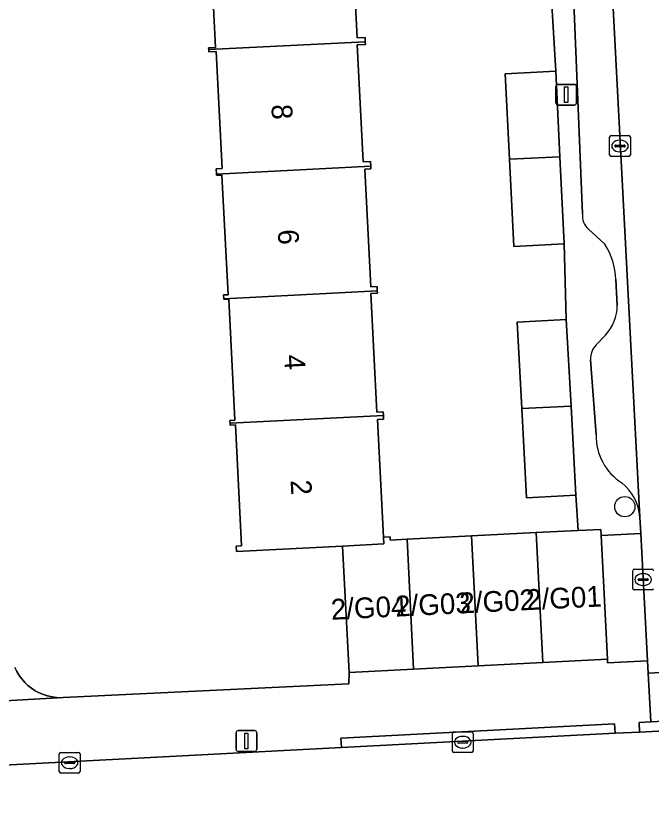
# Model space of a CAD drawing. Extents: x 161084 to 161928, y 385354 to 386522.
# Drawn here: x 161567.76 to 161598.42, y 385454.78 to 385493.46 of the extents above; entities that cross this region are included whole.
import ezdxf

# ---------------------------------------------------------------- set-up
doc = ezdxf.new("R2010")
doc.units = 0
for name, color, linetype in [('IMGEO_Boom', 7, 'Continuous'), ('IMGEO_Erf', 7, 'Continuous'), ('IMGEO_Kolk', 7, 'Continuous'), ('IMGEO_Lichtmast', 7, 'Continuous'), ('IMGEO_Pand', 7, 'Continuous'), ('IMGEO_Pand_nummerreeks', 7, 'Continuous'), ('IMGEO_Parkeervlak_open', 7, 'Continuous'), ('IMGEO_Rijbaan_lokaal_open', 7, 'Continuous'), ('IMGEO_Voetpad_open', 7, 'Continuous')]:
    doc.layers.add(name, color=color, linetype=linetype)

msp = doc.modelspace()

# ---------------------------------------------------------------- linework, layer by layer
at = {"layer": 'IMGEO_Boom'}
msp.add_circle((161597.107, 385469.791), 0.489, dxfattribs=at)
at = {"layer": 'IMGEO_Erf'}
for points in [[(161583.916, 385498.009), (161584.2, 385492.402), (161584.585, 385492.421), (161584.595, 385492.218), (161584.602, 385492.089), (161584.205, 385492.069), (161584.491, 385486.417), (161584.85, 385486.436), (161584.862, 385486.207), (161584.868, 385486.08), (161584.577, 385486.065), (161584.864, 385480.394), (161585.162, 385480.41), (161585.173, 385480.197), (161585.179, 385480.092), (161584.867, 385480.076), (161585.157, 385474.355), (161585.461, 385474.37), (161585.47, 385474.188), (161585.479, 385474.017), (161585.184, 385474.002), (161585.471, 385468.323), (161585.787, 385468.339), (161585.795, 385468.182), (161586.609, 385468.223), (161589.723, 385468.381), (161592.837, 385468.538), (161594.865, 385468.641), (161594.75, 385470.341), (161592.373, 385470.211), (161592.137, 385474.525), (161591.909, 385478.691), (161594.285, 385478.821), (161594.19, 385482.466), (161591.761, 385482.345), (161591.551, 385486.545), (161591.345, 385490.674), (161593.774, 385490.795), (161593.561, 385494.542)], [(161567.694, 385462.035), (161567.789, 385461.84), (161567.902, 385461.654), (161568.03, 385461.48), (161568.174, 385461.317), (161568.331, 385461.168), (161568.502, 385461.034), (161568.683, 385460.915), (161568.875, 385460.813), (161569.074, 385460.729), (161569.281, 385460.662), (161569.493, 385460.615), (161569.708, 385460.586), (161569.924, 385460.577), (161570.036, 385460.58), (161583.798, 385461.252), (161583.812, 385461.8), (161583.504, 385467.89), (161578.379, 385467.63), (161578.366, 385467.888), (161578.63, 385467.901), (161578.335, 385473.74), (161578.077, 385473.727), (161578.073, 385473.814), (161578.066, 385473.954), (161578.304, 385473.966), (161578.009, 385479.804), (161577.772, 385479.792), (161577.77, 385479.823), (161577.761, 385480.003), (161577.977, 385480.014), (161577.685, 385485.786), (161577.418, 385485.773), (161577.415, 385485.831), (161577.403, 385486.08), (161577.694, 385486.095), (161577.408, 385491.748), (161577.049, 385491.73), (161577.044, 385491.836), (161577.04, 385491.928), (161577.381, 385491.944), (161577.088, 385497.745)]]:
    msp.add_lwpolyline(points, dxfattribs=at)
at = {"layer": 'IMGEO_Kolk'}
for p, q in [((161596.374, 385486.761), (161596.374, 385487.613)), ((161596.449, 385487.687), (161597.301, 385487.687)), ((161596.862, 385487.467), (161596.887, 385487.467)), ((161597.375, 385487.613), (161597.375, 385486.761)), ((161596.633, 385487.181), (161596.633, 385487.193)), ((161597.071, 385487.144), (161596.673, 385487.144)), ((161596.676, 385487.23), (161597.074, 385487.23)), ((161597.117, 385487.193), (161597.117, 385487.181)), ((161597.301, 385486.687), (161596.449, 385486.687)), ((161596.885, 385486.907), (161596.86, 385486.907)), ((161597.488, 385465.849), (161597.488, 385466.701)), ((161597.563, 385466.775), (161598.415, 385466.775)), ((161597.976, 385466.555), (161598.001, 385466.555)), ((161597.747, 385466.269), (161597.747, 385466.281)), ((161598.185, 385466.232), (161597.787, 385466.232)), ((161597.79, 385466.318), (161598.188, 385466.318)), ((161598.231, 385466.281), (161598.231, 385466.269)), ((161598.415, 385465.775), (161597.563, 385465.775)), ((161597.999, 385465.995), (161597.974, 385465.995)), ((161588.792, 385458.004), (161588.792, 385458.856)), ((161588.867, 385458.93), (161589.719, 385458.93)), ((161589.793, 385458.856), (161589.793, 385458.004)), ((161589.051, 385458.424), (161589.051, 385458.436)), ((161589.489, 385458.387), (161589.091, 385458.387)), ((161589.094, 385458.473), (161589.492, 385458.473)), ((161589.28, 385458.71), (161589.305, 385458.71)), ((161589.535, 385458.436), (161589.535, 385458.424)), ((161589.303, 385458.15), (161589.278, 385458.15)), ((161569.842, 385457.014), (161569.842, 385457.866)), ((161569.917, 385457.94), (161570.769, 385457.94)), ((161570.33, 385457.72), (161570.355, 385457.72)), ((161570.843, 385457.866), (161570.843, 385457.014)), ((161589.719, 385457.93), (161588.867, 385457.93)), ((161570.101, 385457.434), (161570.101, 385457.446)), ((161570.539, 385457.397), (161570.141, 385457.397)), ((161570.144, 385457.483), (161570.542, 385457.483)), ((161570.585, 385457.446), (161570.585, 385457.434)), ((161570.769, 385456.94), (161569.917, 385456.94)), ((161570.353, 385457.16), (161570.328, 385457.16))]:
    msp.add_line(p, q, dxfattribs=at)
for points in [[(161596.374, 385486.761), (161596.374, 385487.613)], [(161596.449, 385487.687), (161597.301, 385487.687)], [(161597.375, 385487.613), (161597.375, 385486.761)], [(161597.301, 385486.687), (161596.449, 385486.687)], [(161597.488, 385465.849), (161597.488, 385466.701)], [(161597.563, 385466.775), (161598.415, 385466.775)], [(161598.415, 385465.775), (161597.563, 385465.775)], [(161588.792, 385458.004), (161588.792, 385458.856)], [(161588.867, 385458.93), (161589.719, 385458.93)], [(161589.793, 385458.856), (161589.793, 385458.004)], [(161569.842, 385457.014), (161569.842, 385457.866)], [(161569.917, 385457.94), (161570.769, 385457.94)], [(161570.843, 385457.866), (161570.843, 385457.014)], [(161589.719, 385457.93), (161588.867, 385457.93)], [(161570.769, 385456.94), (161569.917, 385456.94)]]:
    msp.add_lwpolyline(points, dxfattribs=at)
for centre, radius, start, end in [((161596.451, 385487.611), 0.0765, 91.552, 178.448), ((161596.451, 385487.611), 0.0765, 91.552, 178.448), ((161597.299, 385487.611), 0.0765, 1.552, 88.448), ((161597.299, 385487.611), 0.0765, 1.552, 88.448), ((161596.673, 385487.19), 0.0403, 85.8775, 175.7526), ((161596.67, 385487.18), 0.0366, 178.938, 274.7102), ((161597.074, 385487.187), 0.043, 264.8664, 352.4533), ((161597.078, 385487.192), 0.0386, 1.7309, 96.639), ((161596.451, 385486.763), 0.0765, 181.552, 268.448), ((161596.451, 385486.763), 0.0765, 181.552, 268.448), ((161597.299, 385486.763), 0.0765, 271.552, 358.448), ((161597.299, 385486.763), 0.0765, 271.552, 358.448), ((161597.565, 385466.699), 0.0765, 91.552, 178.448), ((161597.565, 385466.699), 0.0765, 91.552, 178.448), ((161598.413, 385466.699), 0.0765, 1.552, 88.448), ((161598.413, 385466.699), 0.0765, 1.552, 88.448), ((161597.787, 385466.278), 0.0403, 85.8775, 175.7526), ((161597.784, 385466.268), 0.0366, 178.938, 274.7102), ((161598.188, 385466.275), 0.043, 264.8664, 352.4533), ((161598.192, 385466.28), 0.0386, 1.7309, 96.639), ((161597.565, 385465.851), 0.0765, 181.552, 268.448), ((161597.565, 385465.851), 0.0765, 181.552, 268.448), ((161598.413, 385465.851), 0.0765, 271.552, 358.448), ((161598.413, 385465.851), 0.0765, 271.552, 358.448), ((161588.869, 385458.854), 0.0765, 91.552, 178.448), ((161588.869, 385458.854), 0.0765, 91.552, 178.448), ((161589.717, 385458.854), 0.0765, 1.552, 88.448), ((161589.717, 385458.854), 0.0765, 1.552, 88.448), ((161589.091, 385458.433), 0.0403, 85.8775, 175.7526), ((161589.088, 385458.423), 0.0366, 178.938, 274.7102), ((161589.492, 385458.43), 0.043, 264.8664, 352.4533), ((161589.496, 385458.435), 0.0386, 1.7309, 96.639), ((161588.869, 385458.006), 0.0765, 181.552, 268.448), ((161588.869, 385458.006), 0.0765, 181.552, 268.448), ((161589.717, 385458.006), 0.0765, 271.552, 358.448), ((161589.717, 385458.006), 0.0765, 271.552, 358.448), ((161569.919, 385457.864), 0.0765, 91.552, 178.448), ((161569.919, 385457.864), 0.0765, 91.552, 178.448), ((161570.767, 385457.864), 0.0765, 1.552, 88.448), ((161570.767, 385457.864), 0.0765, 1.552, 88.448), ((161570.141, 385457.443), 0.0403, 85.8775, 175.7526), ((161570.138, 385457.433), 0.0366, 178.938, 274.7102), ((161570.542, 385457.44), 0.043, 264.8664, 352.4533), ((161570.546, 385457.445), 0.0386, 1.7309, 96.639), ((161569.919, 385457.016), 0.0765, 181.552, 268.448), ((161569.919, 385457.016), 0.0765, 181.552, 268.448), ((161570.767, 385457.016), 0.0765, 271.552, 358.448), ((161570.767, 385457.016), 0.0765, 271.552, 358.448)]:
    msp.add_arc(centre, radius, start, end, dxfattribs=at)
for centre, major_axis, ratio, start_param, end_param in [((161596.861, 385487.187), (-0.387, 0.002), 0.722429, 4.712389, 7.853982), ((161596.886, 385487.187), (-0.39, 0.002), 0.717154, 1.570796, 4.712389), ((161597.975, 385466.275), (-0.387, 0.002), 0.722429, 4.712389, 7.853982), ((161598, 385466.275), (-0.39, 0.002), 0.717154, 1.570796, 4.712389), ((161589.279, 385458.43), (-0.387, 0.002), 0.722429, 4.712389, 7.853982), ((161589.304, 385458.43), (-0.39, 0.002), 0.717154, 1.570796, 4.712389), ((161570.329, 385457.44), (-0.387, 0.002), 0.722429, 4.712389, 7.853982), ((161570.354, 385457.44), (-0.39, 0.002), 0.717154, 1.570796, 4.712389)]:
    msp.add_ellipse(centre, major_axis=major_axis, ratio=ratio, start_param=start_param, end_param=end_param, dxfattribs=at)
at = {"layer": 'IMGEO_Lichtmast'}
for p, q in [((161593.883, 385490.159), (161594.673, 385490.159)), ((161594.673, 385490.159), (161593.883, 385490.159)), ((161593.783, 385489.259), (161593.783, 385490.059)), ((161593.783, 385490.059), (161593.783, 385489.259)), ((161594.773, 385490.059), (161594.773, 385489.259)), ((161594.773, 385489.259), (161594.773, 385490.059)), ((161594.673, 385489.159), (161593.883, 385489.159)), ((161593.883, 385489.159), (161594.673, 385489.159)), ((161578.368, 385458.088), (161578.368, 385458.888)), ((161578.368, 385458.888), (161578.368, 385458.088)), ((161578.468, 385458.988), (161579.258, 385458.988)), ((161579.258, 385458.988), (161578.468, 385458.988)), ((161579.358, 385458.888), (161579.358, 385458.088)), ((161579.358, 385458.088), (161579.358, 385458.888)), ((161579.258, 385457.988), (161578.468, 385457.988)), ((161578.468, 385457.988), (161579.258, 385457.988))]:
    msp.add_line(p, q, dxfattribs=at)
for points in [[(161594.203, 385490.034), (161594.353, 385490.034), (161594.353, 385489.284), (161594.203, 385489.284), (161594.203, 385490.034)], [(161578.788, 385458.863), (161578.938, 385458.863), (161578.938, 385458.113), (161578.788, 385458.113), (161578.788, 385458.863)]]:
    msp.add_lwpolyline(points, dxfattribs=at)
for centre, start, end in [((161593.883, 385490.059), 90, 180), ((161593.883, 385490.059), 90, 180), ((161594.673, 385490.059), 0, 90), ((161594.673, 385490.059), 360, 90), ((161593.883, 385489.259), 180, 270), ((161593.883, 385489.259), 180, 270), ((161594.673, 385489.259), 270, 0), ((161594.673, 385489.259), 270, 0), ((161578.468, 385458.888), 90, 180), ((161578.468, 385458.888), 90, 180), ((161579.258, 385458.888), 0, 90), ((161579.258, 385458.888), 360, 90), ((161578.468, 385458.088), 180, 270), ((161578.468, 385458.088), 180, 270), ((161579.258, 385458.088), 270, 0), ((161579.258, 385458.088), 270, 0)]:
    msp.add_arc(centre, 0.1, start, end, dxfattribs=at)
at = {"layer": 'IMGEO_Pand'}
for points in [[(161583.916, 385498.009), (161584.244, 385498.026), (161584.234, 385498.225), (161576.831, 385497.851), (161576.837, 385497.732), (161577.088, 385497.745), (161577.381, 385491.944), (161577.04, 385491.928), (161577.044, 385491.836), (161584.595, 385492.218), (161584.585, 385492.421), (161584.2, 385492.402)], [(161577.044, 385491.836), (161577.049, 385491.73), (161577.408, 385491.748), (161577.694, 385486.095), (161577.403, 385486.08), (161577.415, 385485.831), (161584.862, 385486.207), (161584.85, 385486.436), (161584.491, 385486.417), (161584.205, 385492.069), (161584.602, 385492.089), (161584.595, 385492.218)], [(161593.774, 385490.795), (161591.345, 385490.674), (161591.551, 385486.545), (161593.98, 385486.667)], [(161593.98, 385486.667), (161591.551, 385486.545), (161591.761, 385482.345), (161594.19, 385482.466)], [(161584.577, 385486.065), (161584.868, 385486.08), (161584.862, 385486.207), (161577.415, 385485.831), (161577.418, 385485.773), (161577.685, 385485.786), (161577.977, 385480.014), (161577.761, 385480.003), (161577.77, 385479.823), (161585.173, 385480.197), (161585.162, 385480.41), (161584.864, 385480.394)], [(161584.867, 385480.076), (161585.179, 385480.092), (161585.173, 385480.197), (161577.77, 385479.823), (161577.772, 385479.792), (161578.009, 385479.804), (161578.304, 385473.966), (161578.066, 385473.954), (161578.073, 385473.814), (161585.47, 385474.188), (161585.461, 385474.37), (161585.157, 385474.355)], [(161594.285, 385478.821), (161591.909, 385478.691), (161592.137, 385474.525), (161594.514, 385474.645)], [(161594.514, 385474.645), (161592.137, 385474.525), (161592.373, 385470.211), (161594.75, 385470.341)], [(161585.184, 385474.002), (161585.479, 385474.017), (161585.47, 385474.188), (161578.073, 385473.814), (161578.077, 385473.727), (161578.335, 385473.74), (161578.63, 385467.901), (161578.366, 385467.888), (161578.379, 385467.63), (161583.504, 385467.89), (161585.488, 385467.991), (161585.471, 385468.323)], [(161590.04, 385462.116), (161593.154, 385462.273), (161592.837, 385468.538), (161589.723, 385468.381)], [(161592.837, 385468.538), (161593.154, 385462.273), (161596.268, 385462.431), (161595.966, 385468.397), (161595.951, 385468.696), (161594.865, 385468.641)], [(161586.926, 385461.958), (161586.609, 385468.223), (161585.795, 385468.182), (161585.787, 385468.339), (161585.471, 385468.323), (161585.488, 385467.991), (161583.504, 385467.89), (161583.812, 385461.8)], [(161589.723, 385468.381), (161586.609, 385468.223), (161586.926, 385461.958), (161590.04, 385462.116)]]:
    msp.add_lwpolyline(points, close=True, dxfattribs=at)
at = {"layer": 'IMGEO_Parkeervlak_open'}
for points in [[(161597.838, 385469.29), (161596.219, 385500), (161594.595, 385531.27)], [(161593.042, 385527.739), (161594.413, 385500), (161595.065, 385483.917)], [(161595.354, 385483.181), (161596.144, 385482.452)], [(161596.674, 385480.748), (161596.74, 385479.5)], [(161596.174, 385478.068), (161595.719, 385477.593)], [(161595.456, 385476.878), (161595.725, 385473.249)]]:
    msp.add_lwpolyline(points, dxfattribs=at)
for centre, radius, start, end in [((161595.93, 385483.832), 0.869, 174.3687, 228.5075), ((161593.337, 385480.645), 3.338, 1.7741, 32.7807), ((161594.654, 385479.497), 2.086, 316.7772, 0.0898), ((161596.397, 385476.938), 0.943, 135.9818, 183.6279), ((161598.417, 385473.2), 2.693, 178.963, 237.3103), ((161595.457, 385469.077), 2.391, 5.1012, 50.9461)]:
    msp.add_arc(centre, radius, start, end, dxfattribs=at)
at = {"layer": 'IMGEO_Rijbaan_lokaal_open'}
for points in [[(161594.493, 385533.27), (161594.595, 385531.27), (161596.219, 385500), (161597.838, 385469.29), (161597.88, 385468.494), (161598.204, 385462.35), (161598.235, 385461.758), (161603.364, 385462.015), (161603.012, 385468.475), (161602.647, 385475.158), (161601.292, 385500), (161600.795, 385509.915), (161600.36, 385518.573), (161600.16, 385522.574), (161598.765, 385550.368)], [(161624.618, 385459.918), (161621.197, 385459.746), (161604.552, 385459.269), (161597.818, 385458.919), (161596.64, 385458.858), (161583.443, 385458.171), (161561.024, 385457.005), (161560.918, 385457), (161561.322, 385449.16), (161568.656, 385449.513), (161574.004, 385449.781)]]:
    msp.add_lwpolyline(points, dxfattribs=at)
at = {"layer": 'IMGEO_Voetpad_open'}
for points in [[(161595.065, 385483.917), (161594.413, 385500), (161593.042, 385527.739)], [(161593.561, 385494.542), (161593.774, 385490.795), (161593.98, 385486.667), (161594.19, 385482.466), (161594.285, 385478.821), (161594.514, 385474.645), (161594.75, 385470.341), (161594.865, 385468.641), (161595.951, 385468.696), (161595.966, 385468.397), (161597.88, 385468.494), (161597.838, 385469.29)], [(161596.144, 385482.452), (161595.354, 385483.181)], [(161596.74, 385479.5), (161596.674, 385480.748)], [(161595.719, 385477.593), (161596.174, 385478.068)], [(161595.725, 385473.249), (161595.456, 385476.878)], [(161562.166, 385460.138), (161570.036, 385460.58), (161569.924, 385460.577), (161569.708, 385460.586), (161569.493, 385460.615), (161569.281, 385460.662), (161569.074, 385460.729), (161568.875, 385460.813), (161568.683, 385460.915), (161568.502, 385461.034), (161568.331, 385461.168), (161568.174, 385461.317), (161568.03, 385461.48), (161567.902, 385461.654), (161567.789, 385461.84), (161567.694, 385462.035)]]:
    msp.add_lwpolyline(points, dxfattribs=at)
for points in [[(161596.268, 385462.431), (161596.278, 385462.252), (161598.204, 385462.35), (161597.88, 385468.494), (161595.966, 385468.397)], [(161598.235, 385461.758), (161598.204, 385462.35), (161596.278, 385462.252), (161596.268, 385462.431), (161593.154, 385462.273), (161590.04, 385462.116), (161586.926, 385461.958), (161583.812, 385461.8), (161583.798, 385461.252), (161570.036, 385460.58), (161562.166, 385460.138), (161556.811, 385459.885), (161556.969, 385456.794), (161558.111, 385456.854), (161558.187, 385456.858), (161560.918, 385457), (161561.024, 385457.005), (161583.443, 385458.171), (161583.419, 385458.624), (161596.615, 385459.319), (161596.64, 385458.858), (161597.818, 385458.919), (161597.793, 385459.381), (161598.36, 385459.411)], [(161603.364, 385462.015), (161598.235, 385461.758), (161598.36, 385459.411), (161603.488, 385459.684)], [(161604.527, 385459.739), (161603.488, 385459.684), (161598.36, 385459.411), (161597.793, 385459.381), (161597.818, 385458.919), (161604.552, 385459.269)], [(161596.64, 385458.858), (161596.615, 385459.319), (161583.419, 385458.624), (161583.443, 385458.171)]]:
    msp.add_lwpolyline(points, close=True, dxfattribs=at)
for centre, radius, start, end in [((161595.93, 385483.832), 0.869, 174.3687, 228.5075), ((161593.337, 385480.645), 3.338, 1.7741, 32.7807), ((161594.654, 385479.497), 2.086, 316.7772, 0.0898), ((161596.397, 385476.938), 0.943, 135.9818, 183.6279), ((161598.417, 385473.2), 2.693, 178.963, 237.3103), ((161595.457, 385469.077), 2.391, 5.1012, 50.9461)]:
    msp.add_arc(centre, radius, start, end, dxfattribs=at)

# ---------------------------------------------------------------- texts
at = {"layer": 'IMGEO_Pand_nummerreeks'}
for s, rotation, p in [('8', 272.9277, (161580.064, 385489.181)), ('6', 272.9276, (161580.374, 385483.145)), ('4', 272.9276, (161580.683, 385477.106)), ('2', 272.9276, (161580.992, 385471.068)), ('2/G02', 2.8421, (161589.159, 385464.638)), ('2/G01', 2.8421, (161592.378, 385464.798)), ('2/G04', 2.8421, (161582.96, 385464.331)), ('2/G03', 2.8421, (161586.063, 385464.485))]:
    msp.add_text(s, height=1, rotation=rotation, dxfattribs=at).set_placement(p)

doc.saveas('drawing.dxf')
